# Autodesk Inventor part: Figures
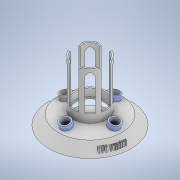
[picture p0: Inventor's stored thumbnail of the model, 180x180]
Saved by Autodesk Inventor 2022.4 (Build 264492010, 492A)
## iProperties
Created: 2021-04
Part Number: Figures
Material: Generic
Document SubType Name: Modeling
Designer: tmass
Density: 1 g/cm^3
Appearance: Default
Vial_radius: 8,500 mm
Vial_number: 4,000 ul
Height_vial_holder: 10,000 mm
Author: tmass
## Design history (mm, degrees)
sketch "Sketch1"
  geometry: C1 r 58 at (0, 0); C2 r 67 at (0, 0); 1 further point
  constraints: 2 centre point, 2 coincident
  dimensions: "d40" = 134 diameter of C2; "d52" = 116 diameter of C1
extrude "Extrusion1" new body sketch "Sketch1" distance "d2" = 5; taper "d3" = 0 deg
sketch "Sketch4"
  geometry: L1 (5, -67)-(5, 67) reference; L2 (5, 0)-(21.742, 0); L3 (21.742, 0)-(5, -67); L4 (5, 58)-(5, -58) reference; L5 (5, -67)-(5, -58); L6 (5, -58)-(19.493, 0); L7 (66.796, -53.944)-(-54.877, -23.539); L8 (-79.212, 0)-(91.13, 0) reference; 1 further point
  constraints: 10 end point, 1 collinear, 1 horizontal, 1 midpoint, 1 parallel, 1 perpendicular, 1 point on line
  dimensions: "d8" = 14.03 deg angle of L2 L7
revolve "Revolution1" sketch "Sketch4" stored, may be unused: angle "d9" = 90 deg
workplane "Work Plane1"
sketch "Sketch5"
  geometry: C1 r 33 at (0, 0); C2 r 30 at (0, 0); C3 r 38 at (0, 0); 1 further point
  constraints: 3 centre point, 3 coincident
  dimensions: "d11" = 66 diameter of C1; "d12" = 60 diameter of C2; "d13" = 5 radial gap between concentric circles of C1 C3
extrude "Extrusion3" cut sketch "Sketch5" extent not by distance; stored distance "d14" = 0; taper "d15" = 0 deg
sketch "Sketch6"
  geometry: C1 r 32 at (0, 0); C2 r 30 at (0, 0); 1 further point
  constraints: 2 centre point, 2 coincident
  dimensions: "d16" = 64 diameter of C1; "d17" = 60 diameter of C2
extrude "Extrusion4" join sketch "Sketch6" distance "d18" = 2; taper "d19" = 0 deg
sketch "Sketch7"
  geometry: C1 r 35 at (0, 0); C2 r 32 at (0, 0) reference; 1 further point
  constraints: 1 centre point, 1 coincident
  dimensions: "d22" = 3 radial gap between concentric circles of C2 C1
extrude "Extrusion5" join sketch "Sketch7" distance "d23" = 100; taper "d24" = 0 deg; dims "d25" = 1.5, "d26" = 0
sketch "Sketch9"
  geometry: L1 (-48.076, 0.345)-(-54.1, 24.456); L2 (-54.1, 24.456)-(-62.347, 22.396); L3 (-62.347, 22.396)-(-56.359, -1.569); L4 (71.975, 5)-(-71.975, 5) reference; L5 (67, 5)-(-67, 5) reference; L6 (-48.076, 0.345)-(-56.359, -1.569); L7 (-35, 113.5)-(-32, 113.5) reference; L8 (-32, 113.5)-(-32, 15.5) reference; L9 (-32, 15.5)-(-30, 15.5) reference; L10 (-30, 11.997)-(-58, 5) reference; L11 (-58, 5)-(-58, 0) reference; L12 (-58, 0)-(-67, 0) reference; L13 (-67, 0)-(-67, 5) reference; L14 (-35, 12.996)-(-35, 113.5) reference; L15 (32, 113.5)-(35, 113.5) reference; L16 (35, 113.5)-(35, 12.996) reference; L17 (35, 12.996)-(67, 5) reference; L18 (67, 5)-(67, 0) reference; L19 (67, 0)-(58, 0) reference; L20 (58, 0)-(58, 5) reference; L21 (58, 5)-(30, 11.997) reference; L22 (30, 15.5)-(32, 15.5) reference; L23 (32, 15.5)-(32, 113.5) reference; L24 (0, 91.108)-(0, -54.991); L25 (-67, 5)-(-35, 12.996) reference; L26 (30, 11.997)-(30, 15.5) reference; L27 (-30, 15.5)-(-30, 11.997) reference; L28 (67, 0)-(-67, 0) reference; L29 (-35, 12.996)-(-67, 5) reference; L30 (-59.119, 9.476)-(-58, 5); 12 further points
  constraints: 12 end point, 3 perpendicular, 2 parallel, 1 collinear, 1 vertical
  dimensions: "d117" = 15.75243 distance from line of L1 L14.start (derived); "d118" = 8.73152 distance from line of L5.end L30 (derived)
revolve "Revolution2" sketch "Sketch9" stored, may be unused: angle "d36" = 360 deg
pattern_circular "Circular Pattern1" dims angle "d38" = 360 deg
sketch "Sketch12"
  geometry: L1 (30.5, 8)-(30.5, -8); L2 (30.5, -8)-(98.5, -8); L3 (113.5, 32)-(113.5, -32) reference; L4 (15.5, 30)-(15.5, -30) reference; L5 (-22.7, 0)-(136.2, 0) reference; L6 (105.5, 2)-(98.5, 8); L7 (105.5, -2)-(98.5, -8); L8 (98.5, 8)-(30.5, 8); L9 (105.5, -2)-(105.5, 2); 3 further points
  constraints: 12 end point, 2 parallel, 1 horizontal, 1 midpoint, 1 perpendicular
  dimensions: "d49" = 15 distance between parallel lines of L4 L1; "d50" = 0 distance from line of point (64.782, 0) L5; "d51" = 16 distance of L1.start L1.end; "d98" = 2 distance from line of L5 L7.start; "d102" = 8 distance between parallel lines of L9 L3; "d110" = 8 distance from line of L2 point (64.782, 0); "d111" = 68 distance of L1.end L2.end; "d112" = 68 distance of L6.end L1.start (= d111); "d113" = 2 distance of point (105.5, 0) L6.start
extrude "Extrusion6" cut sketch "Sketch12" extent not by distance; stored distance "d43" = 0; taper "d44" = 0 deg
pattern_circular "Circular Pattern2" dims angle "d46" = 360 deg
sketch "Sketch13"
  geometry: C1 r 30 at (0, 0) reference; C2 r 64.25 at (0, 0); C3 r 58.75 at (0, 0); 1 further point
  constraints: 2 centre point, 2 coincident
  dimensions: "d53" = 128.5 diameter of C2; "d54" = 117.5 diameter of C3
extrude "Extrusion7" cut sketch "Sketch13" distance "d55" = 4; taper "d56" = 0 deg
sketch "Sketch14"
  geometry: L1 (12.996, 35)-(5, 67) reference; L2 (5, 67)-(-14.766, 86.766); L3 (-14.766, 86.766)-(-14.766, 81.766); L4 (0, 67)-(5, 67) reference; L5 (0, 67)-(5, 67); L6 (-14.766, 81.766)-(0, 67); L7 (-20.318, 0)-(18.549, 0) reference; 2 further points
  constraints: 8 end point, 2 perpendicular, 1 parallel
  dimensions: "d60" = 5 distance of L4.start L4.end (derived); "d61" = 5 distance of L3.end L2.end; "d62" = 5 distance of L1.end L5.start
revolve "Revolution3" sketch "Sketch14" stored, may be unused: angle "d63" = 90 deg
sketch "Sketch16"
  geometry: L1 (32.035, 113.332)-(35.035, 113.332); L2 (35.035, 113.332)-(35.035, 12.828); L3 (35.035, 12.828)-(67.035, 4.832); L4 (67.035, 4.832)-(67.035, -0.168); L5 (67.035, -0.168)-(58.035, -0.168); L6 (58.035, -0.168)-(58.035, 4.832); L7 (58.035, 4.832)-(30.035, 11.828); L8 (30.035, 15.332)-(32.035, 15.332); L9 (32.035, 15.332)-(32.035, 113.332); L10 (0, 91.108)-(0, -54.991); L11 (30.035, 11.828)-(30.035, 15.332); L12 (-63.625, 16.151)-(-61.201, 6.449); L13 (-58.75, 1.011)-(-57.106, 1.422); L14 (-57.106, 1.422)-(-60.953, 16.818); L15 (-60.953, 16.818)-(-63.625, 16.151); L16 (-58.75, 4)-(-58.75, 0) reference; L17 (64.25, 4)-(-64.25, 4) reference; L18 (-58.75, 4)-(-58.75, 0) reference; L19 (-58.75, 4)-(58.75, 4) reference; L20 (-58.75, 1.011)-(-58.75, 4); L21 (-62.347, 22.396)-(-56.359, -1.569) reference; L22 (-58.75, 4)-(-58.75, 7.062); L23 (-58.75, 7.062)-(-61.201, 6.449); L24 (-48.076, 0.345)-(-56.359, -1.569) reference; L25 (-54.1, 24.456)-(-62.347, 22.396) reference; L26 (-48.076, 0.345)-(-54.1, 24.456) reference; L27 (-35, 12.996)-(-67, 5) reference; 5 further points
  constraints: 36 end point, 5 parallel, 3 vertical, 2 collinear, 1 perpendicular
revolve "Revolution4" sketch "Sketch16" stored, may be unused: angle "d72" = 360 deg
pattern_circular "Number of vials" dims angle "d78" = 360 deg
sketch "Sketch17"
  geometry: L1 (122.59, 10)-(30.5, 10); L2 (30.5, 10)-(30.5, -10); L3 (30.5, -10)-(122.59, -10); L4 (122.59, -10)-(122.59, 10); L5 (122.59, 10)-(30.5, -10); L6 (30.5, 10)-(122.59, -10); L7 (113.5, 32)-(113.5, 10); L8 (15.5, 30)-(15.5, -30); L9 (-19.5, 0)-(117, 0); L10 (113.5, 15)-(108.5, 10); L11 (113.5, -15)-(108.5, -10); L12 (113.5, 10)-(113.5, -10); L13 (113.5, -10)-(113.5, -32); L14 (113.5, 32)-(113.5, -32) reference; 3 further points
  constraints: 26 end point, 8 point on line, 2 midpoint, 2 parallel, 1 horizontal, 1 perpendicular
  dimensions: "d81" = 15 distance between parallel lines of L8 L2; "d82" = 0 distance from line of point (76.545, 0) L9; "d83" = 20 distance of L1.end L2.end; "d103" = 5 distance of L10.start L7.end; "d104" = 5 distance of L7.end L10.end; "d106" = 5 distance of L12.end L11.end; "d107" = 5 distance of L12.end L11.start
extrude "Extrusion8" cut sketch "Sketch17" stored distance "d85" = 110.031; taper "d86" = 0 deg
pattern_circular "Circular Pattern4" dims angle "d88" = 360 deg
sketch "Sketch20"
  geometry: A1 r 81.766 centre (0, 0) between (81.766, 0) and (0, 81.766) reference; A2 r 81.766 centre (0, 0) between (81.766, 0) and (0, 81.766); 1 further point
  constraints: 4 point on circle, 1 centre point, 1 concentric, 1 other
emboss "Emboss4" sketch "Sketch20" dims "d16" = 64, "d108" = 2, "d109" = 0
sketch "Sketch22"
  geometry: L1 (-89.343, -89.343)-(101.761, 101.761); L2 (0, -124.416)-(0, 136.528) reference; L3 (143.435, 0)-(-130.711, 0) reference; C1 r 7.071 at (0, 0); 1 further point
  constraints: 2 end point, 1 centre point, 1 coincident, 1 point on line
  dimensions: "d120" = 45 deg angle of L3 L1
extrude "Extrusion9" join sketch "Sketch22" distance "d121" = 10; taper "d122" = 0 deg
body "Solid1"
node "Project Cut Edges1"
other parameters: "d10" = 13.5, "sa_0" = 4
